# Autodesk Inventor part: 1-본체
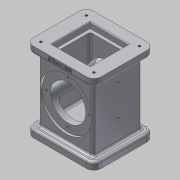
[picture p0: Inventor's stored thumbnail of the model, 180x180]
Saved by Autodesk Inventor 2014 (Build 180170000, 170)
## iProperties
Created: 2017-08
Part Number: 1-본체
Material: 알루미늄 6061
Document SubType Name: Modeling
Designer: 601-04
Density: 2.71 g/cm^3
Appearance: 알루미늄 - 평지
Mass: 871.037 g
Surface Area: 645.524 cm^2
Volume: 321.416 cm^3
Author: 601-04
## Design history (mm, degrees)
sketch "스케치1"
  geometry: L1 (-46, 41)-(46, 41); L2 (46, 41)-(46, -41); L3 (46, -41)-(-46, -41); L4 (-46, -41)-(-46, 41); L5 (-46, 41)-(46, -41); L6 (46, 41)-(-46, -41); 1 further point
  constraints: 12 end point, 2 midpoint, 2 parallel, 1 horizontal, 1 perpendicular
  dimensions: "d0" = 92 distance of L2.end L3.end; "d1" = 82 distance of L1.end L2.end
extrude "돌출1" new body sketch "스케치1" distance "d2" = 10; taper "d3" = 0 deg
sketch "스케치2"
  geometry: L1 (-37, 33)-(37, 33); L2 (37, 33)-(37, -33); L3 (37, -33)-(-37, -33); L4 (-37, -33)-(-37, 33); L5 (-37, 33)-(37, -33); L6 (37, 33)-(-37, -33); 1 further point
  constraints: 12 end point, 2 midpoint, 2 parallel, 1 horizontal, 1 perpendicular
  dimensions: "d4" = 74 distance of L2.end L3.end; "d5" = 66 distance of L1.end L2.end
extrude "돌출2" join sketch "스케치2" distance "d6" = 88; taper "d7" = 0 deg
sketch "스케치3"
  geometry: L1 (-46, 41)-(46, 41); L2 (46, 41)-(46, -41); L3 (46, -41)-(-46, -41); L4 (-46, -41)-(-46, 41); L5 (-46, 41)-(46, -41); L6 (46, 41)-(-46, -41); 1 further point
  constraints: 12 end point, 2 midpoint, 2 parallel, 1 horizontal, 1 perpendicular
  dimensions: "d8" = 92 distance of L2.end L3.end; "d9" = 82 distance of L1.end L2.end
extrude "돌출3" join sketch "스케치3" distance "d10" = 10; taper "d11" = 0 deg
sketch "스케치4"
  geometry: L1 (-22, 22)-(22, 22); L2 (22, 22)-(22, -22); L3 (22, -22)-(-22, -22); L4 (-22, -22)-(-22, 22); L5 (-22, 22)-(22, -22); L6 (22, 22)-(-22, -22); 1 further point
  constraints: 12 end point, 2 midpoint, 2 parallel, 1 horizontal, 1 perpendicular
  dimensions: "d12" = 44 distance of L2.end L3.end; "d13" = 44 distance of L1.end L2.end
extrude "돌출4" cut sketch "스케치4" distance "d14" = 82; taper "d15" = 0 deg
sketch "스케치5"
  geometry: L1 (26, 26)-(-26, 26); L2 (-26, 26)-(-26, -26); L3 (-26, -26)-(26, -26); L4 (26, -26)-(26, 26); L5 (26, 26)-(-26, -26); L6 (-26, 26)-(26, -26); 1 further point
  constraints: 12 end point, 2 midpoint, 2 parallel, 2 perpendicular, 1 horizontal
  dimensions: "d16" = 52 distance of L3.end L2.end
extrude "돌출5" cut sketch "스케치5" distance "d17" = 8; taper "d18" = 0 deg
sketch "스케치6"
  geometry: L1 (-24, 24)-(24, 24); L2 (24, 24)-(24, -24); L3 (24, -24)-(-24, -24); L4 (-24, -24)-(-24, 24); L5 (-24, 24)-(24, -24); L6 (24, 24)-(-24, -24); 1 further point
  constraints: 12 end point, 2 midpoint, 2 parallel, 1 horizontal, 1 perpendicular
  dimensions: "d19" = 48 distance of L2.end L3.end; "d20" = 48 distance of L1.end L2.end
extrude "돌출6" cut sketch "스케치6" distance "d21" = 16; taper "d22" = 0 deg
sketch "스케치7"
  geometry: C1 r 24 at (37, 44); 1 further point
  constraints: 1 centre point, 1 vertical alignment
  dimensions: "d23" = 48 diameter of C1; "d24" = 54 distance of point (37, -10) C1.centre
extrude "돌출7" cut sketch "스케치7" stored distance "d25" = 8; taper "d26" = 0 deg
sketch "스케치8"
  geometry: C1 r 24 at (37, 44) reference; C2 r 35 at (37, 44); 1 further point
  constraints: 1 centre point, 1 coincident
  dimensions: "d27" = 70 diameter of C2
extrude "돌출8" cut sketch "스케치8" distance "d28" = 3; taper "d29" = 0 deg
fillet "모깎기1" dims "d30" = 10
sketch "스케치9"
  geometry: A1 r 10 centre (36, -31) between (36, -41) and (46, -31) reference; A2 r 10 centre (36, 31) between (46, 31) and (36, 41) reference; A3 r 10 centre (-36, 31) between (-36, 41) and (-46, 31) reference; A4 r 10 centre (-36, -31) between (-46, -31) and (-36, -41) reference; 5 further points
  constraints: 4 coincident
hole "구멍1" sketch "스케치9" at (-36, 31), (36, 31), (36, -31), (-36, -31) diameter "d31" = 3.242; stored, may be unused: countersink angle "d35" = 90 deg, drill point angle "d37" = 118 deg; dims "d32" = 4, "d33" = 4, "d34" = 2, "d36" = 6
sketch "스케치10"
  geometry: A1 r 10 centre (36, 31) between (46, 31) and (36, 41) reference; A2 r 10 centre (-36, 31) between (-36, 41) and (-46, 31) reference; A3 r 10 centre (-36, -31) between (-46, -31) and (-36, -41) reference; A4 r 10 centre (36, -31) between (36, -41) and (46, -31) reference; 5 further points
  constraints: 4 coincident
hole "구멍2" sketch "스케치10" at (-36, 31), (36, 31), (36, -31), (-36, -31) diameter "d38" = 3.242; stored, may be unused: countersink angle "d42" = 90 deg, drill point angle "d44" = 118 deg; dims "d39" = 4, "d40" = 4, "d41" = 2, "d43" = 6
sketch "스케치11" dims "d45" = 58
  geometry: C1 r 35 at (0, 0) reference; 3 further points
  constraints: 2 vertical alignment, 1 coincident, 2 other
hole "구멍3" sketch "스케치11" at (0, 29) diameter "d46" = 3.242; stored, may be unused: countersink angle "d50" = 90 deg, drill point angle "d52" = 118 deg; dims "d47" = 4, "d48" = 4, "d49" = 2, "d51" = 6
sketch "스케치12"
  geometry: L1 (0, 66)-(0, 0) reference; L2 (-88, 66)-(-88, 0) reference; L3 (-88, 33)-(0, 33); L4 (10, 64)-(10, 2) reference; 3 further points
  constraints: 2 end point, 2 midpoint, 2 point on line
  dimensions: "d56" = 38 distance from line of L4 point (-28, 33); "d57" = 42 distance of point (-70, 33) point (-28, 33)
hole "구멍4" sketch "스케치12" at (-28, 33), (-70, 33) diameter "d58" = 4.134; stored, may be unused: countersink angle "d62" = 90 deg, drill point angle "d64" = 118 deg; dims "d59" = 4, "d60" = 4, "d61" = 2, "d63" = 6
fillet "모깎기2" dims "d65" = 3
fillet "모깎기3" dims "d66" = 3
fillet "모깎기4" dims "d67" = 3
chamfer "모따기1" distance "d68" = 1; stored, may be unused: second distance "d69" = 2, angle "d70" = 45 deg
fillet "모깎기5" dims "d71" = 3
sketch "스케치13"
  geometry: L1 (0, 0)-(72, 0) reference; L2 (-10, 0)-(-10, -7) reference; 2 further points
  constraints: 1 other
  dimensions: "d72" = 46 distance from line of L2 point (36, -4); "d73" = 4 distance from line of L1 point (36, -4)
feature "엠보싱1" sketch "스케치13" dims "d0" = 92, "d1" = 82, "d8" = 92, "d9" = 82, "d74" = 0.5, "d75" = 0
fillet "모깎기6" dims "d76" = 3
fillet "모깎기7" dims "d77" = 3
node "솔리드1"
pattern_circular "원형 패턴1" dims angle "d54" = 360 deg
mirror "대칭1"
